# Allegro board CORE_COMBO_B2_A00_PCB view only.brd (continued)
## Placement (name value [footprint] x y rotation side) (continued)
PC5842  -  [NB_C0402_SMALL]  72.96 108.83 90 top
PC5843  -  [NB_C0402_SMALL]  68.72 123.05 90 top
PC5901  -  [NB_C0402_SMALL]  106.01 125.08 90 top
PC5902  -  [NB_C0402_SMALL]  115.13 128.13 270 top
PC5903  -  [NB_C0805_H55_SMALL]  120.2 131.05 270 top
PC5904  -  [NB_C0805_H55_SMALL]  116.14 127.75 270 bottom
PC5905  -  [NB_C0805_H55_SMALL]  112.08 127.88 270 bottom
PC5906  -  [NB_C0805_H55_SMALL]  121.98 131.05 270 top
PC5908  -  [C3528_H79]  117.39 129.66 90 top
PC5909  -  [NB_C0603_H35_SMALL]  108.93 130.09 180 top
PC5910  -  [NB_C0402_SMALL]  126.25 128.03 180 top
PC5911  -  [NB_C0603_H39_SMALL]  126.22 130.39 180 top
PC5912  -  [NB_C7343D_H79]  118.68 119.92 270 top
PC5913  -  [NB_C0603_H39_SMALL]  126.22 129.12 180 top
PC5914  -  [NB_C0603_H35_SMALL]  119.14 125.67 0 top
PC5915  -  [NB_C0402_SMALL]  123 128.39 90 top
PC5916  -  [NB_C0402_SMALL]  60.03 96.73 0 top
PC5917  -  [NB_C0805_H55_SMALL]  69.45 89.47 0 bottom
PC5918  -  [NB_C0805_H55_SMALL]  57.34 95.95 180 top
PC5919  -  [NB_C0805_H55_SMALL]  60.01 98.16 0 top
PC5920  -  [NB_C0805_H55_SMALL]  59.5 101.97 0 top
PC5921  -  [C3528_H79]  69.2 94.64 270 bottom
PC5922  -  [C3528_H79]  60.54 97.32 180 bottom
PC5923  -  [NB_C0603_H35_SMALL]  121.22 125.85 90 top
PC5924  -  [NB_C0603_H35_SMALL]  124.52 126.23 90 bottom
PC5925  -  [NB_C0402_SMALL]  64.96 90.67 0 top
PC5926  -  [NB_C0603_H35_SMALL]  56.96 92.19 180 top
PC5927  -  [NB_C7343D_H79]  68.51 101.21 0 top
PC5928  -  [NB_C0603_H35_SMALL]  62.28 99.83 180 top
PC5929  -  [NB_C7343D_H79]  114.87 120.26 270 bottom
PC5930  -  [NB_C7343D_H79]  68.29 100.29 0 bottom
PC5931  -  [C3528_H79]  65.52 94.64 270 bottom
PC5932  -  [C3528_H79]  119.42 131.2 180 bottom
PC6001  -  [NB_C0603_H39_SMALL]  114.49 110.86 0 top
PC6003  -  [NB_C0603_H39_SMALL]  114.49 112.13 0 top
PC6004  -  [NB_C0603_H39_SMALL]  114.49 109.59 0 top
PC6005  -  [NB_C0603_H39_SMALL]  107.63 113.66 180 top
PC6006  -  [NB_C0603_H39_SMALL]  107.63 114.93 180 top
PC6007  -  [NB_C0603_H39_SMALL]  107.63 116.2 180 top
PC6008  -  [NB_C0603_H39_SMALL]  114.49 113.37 0 top
PC6009  -  [NB_C0603_H39_SMALL]  107.63 109.88 180 top
PC6010  -  [NB_C0603_H39_SMALL]  114.49 114.62 0 top
PC6011  -  [NB_C0603_H39_SMALL]  107.63 112.42 180 top
PC6012  -  [NB_C0603_H39_SMALL]  107.63 111.15 180 top
PC6013  -  [NB_C0603_H39_SMALL]  118.04 91.3 180 top
PC6014  -  [NB_C0603_H39_SMALL]  108.34 92.88 0 top
PC6015  -  [NB_C0603_H39_SMALL]  106.17 98.16 0 top
PC6016  -  [NB_C0603_H39_SMALL]  103.96 98.16 0 top
PC6017  -  [NB_C0603_H39_SMALL]  95.06 97.65 90 top
PC6018  -  [NB_C0603_H39_SMALL]  93.66 97.65 90 top
PC6019  -  [NB_C0603_H39_SMALL]  108.34 91.61 0 top
PC6020  -  [NB_C0603_H39_SMALL]  103.54 89.05 180 top
PC6021  -  [NB_C0603_H39_SMALL]  106.11 89.02 0 top
PC6022  -  [NB_C0603_H39_SMALL]  108.34 95.42 0 top
PC6023  -  [NB_C0603_H39_SMALL]  108.34 94.15 0 top
PC6024  -  [NB_C0603_H39_SMALL]  122.36 98.24 180 top
PC6025  -  [NB_C0603_H39_SMALL]  123.02 111.11 180 top
PC6026  -  [NB_C0603_H39_SMALL]  98.23 90.08 270 top
PC6027  -  [NB_C0603_H39_SMALL]  96.99 90.08 270 top
PC6029  -  [NB_C0603_H39_SMALL]  108.34 90.34 0 top
PC6035  -  [NB_C0603_H39_SMALL]  114.49 113.4 0 bottom
PC6038  -  [NB_C0603_H39_SMALL]  114.49 112.13 0 bottom
PC6040  -  [NB_C0603_H39_SMALL]  114.49 109.64 0 bottom
PC6041  -  [NB_C0603_H39_SMALL]  114.49 110.88 0 bottom
PC6042  -  [NB_C0603_H39_SMALL]  120.97 90.79 0 top
PC6043  -  [NB_C0603_H39_SMALL]  120.97 92.01 0 top
PC6044  -  [NB_C0603_H39_SMALL]  92.34 89.24 270 top
PC6045  -  [NB_C0603_H39_SMALL]  91.12 89.24 270 top
PC6046  -  [NB_C0603_H39_SMALL]  81.85 96.38 90 bottom
PC6047  -  [NB_C0603_H39_SMALL]  80.58 96.38 90 bottom
PC6048  -  [NB_C0603_H39_SMALL]  83.12 96.38 90 bottom
PC6049  -  [NB_C0603_H39_SMALL]  84.39 96.38 90 bottom
PC6050  -  [NB_C0603_H39_SMALL]  89.54 96.37 90 bottom
PC6051  -  [NB_C0603_H39_SMALL]  88.27 96.37 90 bottom
PC6052  -  [NB_C0603_H39_SMALL]  86.94 96.37 90 bottom
PC6053  -  [NB_C0603_H39_SMALL]  85.67 96.37 90 bottom
PC6056  -  [NB_C0603_H39_SMALL]  109.36 118.61 90 bottom
PC6057  -  [NB_C0603_H39_SMALL]  111.8 118.61 90 bottom
PC6058  -  [NB_C0603_H39_SMALL]  112.84 95.37 180 top
PC6059  -  [NB_C0603_H39_SMALL]  112.84 94.12 180 top
PC6060  -  [NB_C0603_H39_SMALL]  112.84 92.88 180 top
PC6061  -  [NB_C0603_H39_SMALL]  112.84 91.63 180 top
PC6062  -  [NB_C0603_H39_SMALL]  120.97 94.45 0 top
PC6063  -  [NB_C0603_H39_SMALL]  115.81 93.82 0 top
PC6064  -  [NB_C0603_H39_SMALL]  115.81 92.57 0 top
PC6065  -  [NB_C0603_H39_SMALL]  115.81 91.3 0 top
PC6066  -  [NB_C0603_H39_SMALL]  85.91 89.65 270 bottom
PC6067  -  [NB_C0603_H39_SMALL]  87.16 89.65 270 bottom
PC6068  -  [NB_C0603_H39_SMALL]  90.87 89.65 270 bottom
PC6069  -  [NB_C0603_H39_SMALL]  89.63 89.65 270 bottom
PC6070  -  [NB_C0603_H39_SMALL]  88.4 89.65 270 bottom
PC6071  -  [NB_C0603_H39_SMALL]  92.1 89.65 270 bottom
PC6072  -  [NB_C0603_H39_SMALL]  120.97 93.23 0 top
PC6073  -  [NB_C0603_H39_SMALL]  82.1 89.65 270 bottom
PC6074  -  [NB_C0603_H39_SMALL]  83.37 89.65 270 bottom
PC6075  -  [NB_C0603_H39_SMALL]  84.64 89.65 270 bottom
PC6076  -  [C0201]  123.02 110.12 180 top
PC6077  -  [C0201]  123.02 109.39 180 top
PC6078  -  [C0201]  124.12 97.12 270 top
PC6079  -  [C0201]  124.45 89.12 0 top
PC6080  -  [C0201]  124.45 90.64 0 top
PC6081  -  [C0201]  124.45 89.85 0 top
PC6082  -  [C0201]  124.12 98.49 0 top
PC6083  -  [C0201]  114.87 97.04 0 top
PC6084  -  [C0201]  118.04 97.68 180 top
PC6085  -  [C0201]  114.62 89.52 180 top
PC6086  -  [C0201]  116.14 95.16 180 top
PC6087  -  [C0201]  117.54 88.79 180 top
PC6088  -  [C0201]  114.87 97.8 0 top
PC6089  -  [C0201]  118.68 95.9 180 top
PC6090  -  [C0201]  112.58 96.36 180 top
PC6091  -  [C0201]  114.87 95.57 0 top
PC6092  -  [C0201]  117.41 95.9 180 top
PC6093  -  [C0201]  94.22 89.47 270 top
PC6094  -  [C0201]  108.52 98.16 90 top
PC6095  -  [C0201]  109.28 98.16 90 top
PC6096  -  [C0201]  94.96 89.47 270 top
PC6097  -  [C0201]  107.76 98.16 90 top
PC6098  -  [C0201]  110.04 98.16 90 top
PC6099  -  [C0201]  98.87 93.46 270 top
PC6100  -  [C0201]  99.21 96.84 90 top
PC6101  -  [C0201]  98.46 96.84 90 top
PC6102  -  [C0201]  97.6 93.46 270 top
PC6103  -  [C0201]  117.41 95.16 180 top
PC6104  -  [C0201]  114.87 94.81 0 top
PC6105  -  [C0201]  114.62 90.29 180 top
PC6106  -  [C0201]  116.14 95.9 180 top
PC6107  -  [C0201]  113.63 97.75 180 top
PC6108  -  [C0201]  118.68 95.16 180 top
PC6109  -  [C0201]  119.06 89.54 0 top
PC6110  -  [C0201]  119.06 90.29 0 top
PC6111  -  [C0201]  117.54 89.52 180 top
PC6112  -  [C0201]  116.27 88.79 0 top
PC6113  -  [C0201]  93.48 89.47 270 top
PC6114  -  [C0201]  99.25 90.11 270 top
PC6115  -  [C0201]  93.61 92.01 270 bottom
PC6116  -  [C0201]  91.76 96.51 90 bottom
PC6117  -  [C0201]  116.14 97.8 180 top
PC6118  -  [C0201]  116.27 89.52 0 top
PC6119  -  [C0201]  113.63 98.47 180 top
PC6120  -  [C0201]  117.54 90.29 180 top
PC6121  -  [C0201]  116.27 90.29 0 top
PC6122  -  [C0201]  114.62 88.79 180 top
PC6123  -  [NB_C0603_H39_SMALL]  118.04 92.57 180 top
PC6125  -  [NB_C0603_H39_SMALL]  124.24 95.87 0 top
PC6126  -  [NB_C0603_H39_SMALL]  114.49 114.67 0 bottom
PC6127  -  [C0201]  119.06 88.79 0 top
PC6128  -  [C0201]  120.64 98.59 0 top
PC6129  -  [C0201]  120.64 97.85 0 top
PC6130  -  [NB_C0603_H39_SMALL]  118.04 93.82 180 top
PC6131  -  [C0201]  120.64 97.12 0 top
PC6132  -  [NB_C0603_H39_SMALL]  110.58 118.61 90 bottom
PC6133  -  [NB_C0603_H39_SMALL]  122.03 96 180 top
PC6134  -  [C0201]  120.2 96.15 0 top
PC6135  -  [C0201]  120.2 95.42 0 top
PC6136  -  [NB_C0603_H39_SMALL]  123.02 112.33 180 top
PC6137  -  [NB_C0603_H39_SMALL]  123.02 114.77 180 top
PC6138  -  [C0201]  116.14 98.54 180 top
PC6139  -  [NB_C0603_H39_SMALL]  90.78 96.37 90 bottom
PC6140  -  [NB_C0603_H39_SMALL]  129.1 114.75 0 top
PC6141  -  [C0201]  114.87 98.54 0 top
PC6142  -  [C0201]  114.87 96.3 0 top
PC6143  -  [NB_C0603_H39_SMALL]  123.02 113.55 180 top
PC6144  -  [NB_C0603_H39_SMALL]  129.1 113.53 0 top
PC6145  -  [NB_C0603_H39_SMALL]  129.1 112.26 0 top
PC6146  -  [NB_C0603_H39_SMALL]  129.1 110.99 0 top
PC6147  -  [NB_C0603_H39_SMALL]  129.09 109.74 0 top
PC7401  -  [NB_C0603_H39_SMALL]  188.58 24.91 180 top
PC7403  -  [NB_C0603_H39_SMALL]  183.6 22.42 180 bottom
PC7404  -  [NB_C0603_H34_SMALL]  190.03 22.87 270 top
PC7405  -  [NB_C0402_SMALL]  191.2 23.48 180 bottom
PC7406  -  [NB_C0402_SMALL]  195.77 24.93 90 top
PC7407  -  [R0603_H24]  187.31 26.94 270 top
PC7409  -  [NB_C0603_H39_SMALL]  186.04 24.91 0 top
PD5101  -  [ESD_2P_33_39X24_H17]  163.51 32.12 180 bottom
PD5102  -  [ESD_2P_33_39X24_H17]  163.51 33.52 180 bottom
PD5103  -  [ESD_2P_33_39X24_H17]  163.51 34.79 180 bottom
PD5201  -  [POWERDI5_3P_157X256]  221.85 24.25 90 top
PD5202  -  [POWERDI5_3P_157X256]  203.01 26.49 0 top
PD5205  -  [POWERDI5_3P_157X256]  165.9 26.41 180 top
PD5206  -  [SOT323]  228.77 31.88 90 top
PH5801  -  [NB_R0402_H24_SMALL]  60.01 90.67 0 top
PH5802  -  [R0402]  122.74 116.83 270 top
PH5803  -  [R0402]  108.01 118.22 90 top
PH5804  -  [NB_R0402_H24_SMALL]  108.52 125.08 90 top
PH5805  -  [R0402]  71.94 90.67 180 top
PJP6  -  [1MM_OPEN_5MIL_M1M2]  269.81 49.14 90 top
PJP7  -  [1MM_OPEN_5MIL_M1M2]  242.07 65.32 180 top
PJP10  -  [1MM_OPEN_5MIL_M1M2]  40.7 104.38 0 top
PJP802  -  [1MM_OPEN_5MIL_M1M2]  196.58 39.82 270 bottom
PJP803  -  [1MM_OPEN_5MIL_M1M2]  35.37 104.38 0 top
PJP805  -  [1MM_OPEN_5MIL_M1M2]  210.63 147.56 180 top
PJP3301  -  [1MM_OPEN_5MIL_M1M2]  183.07 123.81 0 top
PJP5201  -  [NB_PWR_FB_SHORT_PT]  212.91 23.74 0 top
PJP5202  -  [NB_PWR_FB_SHORT_PT]  214.69 23.74 180 top
PJP5203  -  [NB_PWR_FB_SHORT_PT]  177.35 31.1 180 top
PJP5204  -  [NB_PWR_FB_SHORT_PT]  175.58 31.1 0 top
PJP5301  -  [3MM_OPEN_5MIL_M1M2]  187.58 76.8 90 top
PJP5302  -  [3MM_OPEN_5MIL_M1M2]  205.48 49.39 90 top
PJP5303  -  [NB_PWR_FB_SHORT_PT]  179 72.89 180 bottom
PJP5304  -  [NB_PWR_FB_SHORT_PT]  179 74.28 180 bottom
PJP5305  -  [NB_PWR_FB_SHORT_PT]  200.47 48.38 0 top
PJP5306  -  [1MM_OPEN_5MIL_M1M2]  198.56 62.6 0 bottom
PJP5307  -  [1MM_OPEN_5MIL_M1M2]  191.32 67.17 90 top
PJP5308  -  [3MM_OPEN_5MIL_M1M2]  205.48 55.23 90 top
PJP5401  -  [3MM_OPEN_5MIL_M1M2]  93.34 72.38 90 top
PJP5402  -  [1MM_OPEN_5MIL_M1M2]  88.2 48.63 90 top
PJP5403  -  [1MM_OPEN_5MIL_M1M2]  92.01 52.95 90 top
PJP5404  -  [3MM_OPEN_5MIL_M1M2]  94.87 66.79 90 top
PJP5501  -  [3MM_OPEN_5MIL_M1M2]  144.71 118.48 0 top
PJP5502  -  [3MM_OPEN_5MIL_M1M2]  136.33 119.56 0 bottom
PJP5601  -  [1MM_OPEN_5MIL_M1M2]  170.29 71.87 0 bottom
PJP5602  -  [2MM_OPEN_5MIL_M1M2]  171.54 87.58 270 bottom
PJP5603  -  [1MM_OPEN_5MIL_M1M2]  173.98 107.68 90 bottom
PJP5604  -  [2MM_OPEN_5MIL_M1M2]  173.67 92.93 0 bottom
PJP5701  -  [1MM_OPEN_5MIL_M1M2]  211.9 62.6 0 top
PJP5702  -  [1MM_OPEN_5MIL_M1M2]  217.03 56.45 270 top
PJP5703  -  [1MM_OPEN_5MIL_M1M2]  190.05 103.87 180 top
PJP5704  -  [1MM_OPEN_5MIL_M1M2]  185.48 114.03 270 top
PJP5705  -  [1MM_OPEN_5MIL_M1M2]  211.01 48.63 90 top
PJP5706  -  [1MM_OPEN_5MIL_M1M2]  216.72 48.58 270 top
PJP5707  -  [1MM_OPEN_5MIL_M1M2]  65.85 127.12 90 top
PJP5708  -  [1MM_OPEN_5MIL_M1M2]  69.96 130.93 0 top
PJP5806  -  [1MM_OPEN_5MIL_M1M2]  160.06 125.57 180 bottom
PJP5809  -  [1MM_OPEN_5MIL_M1M2]  153.48 65.27 90 bottom
PJP5810  -  [3MM_OPEN_5MIL_M1M2]  158.56 36.95 270 top
PJP5811  -  [1MM_OPEN_5MIL_M1M2]  200.21 144.77 270 bottom
PJP5812  -  [1MM_OPEN_5MIL_M1M2]  196.91 50.71 270 bottom
PJP5813  -  [1MM_OPEN_5MIL_M1M2]  84.59 111.32 270 bottom
PJP5815  -  [1MM_OPEN_5MIL_M1M2]  90.49 117.59 0 top
PJP5901  -  [NB_PWR_FB_SHORT_PT]  112.46 121.53 90 top
PJP5902  -  [NB_PWR_FB_SHORT_PT]  112.46 117.97 270 top
PJP5903  -  [NB_PWR_FB_SHORT_PT]  126.17 120.64 90 top
PJP5904  -  [NB_PWR_FB_SHORT_PT]  126.17 117.84 270 top
PJP5905  -  [NB_PWR_FB_SHORT_PT]  66.99 94.99 180 top
PJP5906  -  [NB_PWR_FB_SHORT_PT]  70.55 94.99 0 top
PJP5908  -  [2MM_OPEN_5MIL_M1M2]  150.43 114.25 270 top
PJP5909  -  [1MM_OPEN_5MIL_M1M2]  38.93 116.13 180 top
PJP5911  -  [3MM_OPEN_5MIL_M1M2]  186.12 81.31 180 top
PJP5912  -  [1MM_OPEN_5MIL_M1M2]  93.15 115.69 270 top
PJP5913  -  [1MM_OPEN_5MIL_M1M2]  69.96 130.93 180 bottom
PL5101  -  [L0805_H41]  155.51 29.71 0 top
PL5102  -  [L0805_H41]  155.51 27.55 0 top
PL5103  -  [NB_L0603_H37_SMALL]  241.74 41.9 270 top
PL5104  -  [L0805_H41]  29.91 91.18 0 top
PL5201  -  [L0805_H41]  224.47 32.75 90 top
PL5202  -  [NB_INDUCTOR_2P_427X394]  198.18 38.34 180 top
PL5301  -  [NB_INDUCTOR_2P_287X260_H94]  186.62 73.14 0 bottom
PL5302  -  [L0805_H41]  182.18 61.71 180 top
PL5303  -  [L0805_H41]  182.18 59.55 180 top
PL5304  -  [INDUCTOR_2P_287X260]  198.44 54.34 0 top
PL5401  -  [L0805_H41]  78.93 60.44 270 top
PL5402  -  [INDUCTOR_2P_287X260]  83.88 70.6 270 top
PL5501  -  [L0805_H41]  133.52 127.04 270 bottom
PL5502  -  [INDUCTOR_2P_213X205]  133.92 118.48 270 top
PL5601  -  [INDUCTOR_2P_150X150_CYN]  172.27 82.67 90 bottom
PL5602  -  [INDUCTOR_2P_150X150_CYN]  172.13 97.8 270 bottom
PL5701  -  [INDUCTOR_2P_79X63_CY]  218.12 60.64 0 top
PL5702  -  [INDUCTOR_2P_79X63_CY]  188.91 112.13 90 top
PL5703  -  [INDUCTOR_2P_79X63_CY]  217.96 52.95 0 top
PL5704  -  [INDUCTO_2P_98X79_CYNTEC_H47]  71.29 138.18 0 top
PL5901  -  [INDUCTOR_2P_278X260_H118]  112.46 119.75 270 top
PL5902  -  [L0805_H41]  125.06 132.07 0 top
PL5903  -  [L0805_H41]  128.38 131.05 90 top
PL5904  -  [L0805_H41]  67.88 83.3 270 bottom
PL5905  -  [INDUCTOR_2P_197X185]  126.18 119.23 270 top
PL5906  -  [INDUCTOR_2P_278X260_H118]  68.77 94.99 0 top
PL7401  -  [L1008_TAIYO_H47]  187.16 22.95 180 top
PQ5101  -  [SOT23_H43]  244.66 41.39 0 top
PQ5102  -  [SOT23_FAIR]  248.8 39.87 90 top
PQ5103  -  [SOIC_8P_50_196X236]  70.62 81.27 180 top
PQ5104  -  [SOT666_H20]  75.37 68.92 0 top
PQ5105  -  [SOT23]  71.82 87.36 270 top
PQ5106  -  [SOT363_PHILIPS]  72.83 71.24 0 top
PQ5201  -  [POWER33_5P]  224.34 28.56 90 top
PQ5202  -  [SOT363_PHILIPS]  251.01 26.79 180 top
PQ5203  -  [SOT23]  247.84 24.12 90 top
PQ5204  -  [SOT23]  236.79 24.12 90 top
PQ5205  -  [SOT23]  240.09 24.12 90 top
PQ5206  -  [SOT23]  233.49 24.12 90 top
PQ5207  -  [SOT23]  230.06 24.12 90 top
PQ5208  -  [POWER33_5P]  208.21 25.77 0 top
PQ5209  -  [SOT23_2D4_H43]  198.82 24.12 0 top
PQ5210  -  [SOT363_PHILIPS]  257.36 26.79 180 top
PQ5211  -  [SOT23_2D4_H43]  243.52 24.12 0 top
PQ5212  -  [SOT23_2D4_H43]  248.35 30.6 90 top
PQ5213  -  [SOT23]  254.32 24.12 90 top
PQ5214  -  [SOT363_PHILIPS]  250.25 33.77 270 top
PQ5215  -  [SOT23_2D4_H43]  254.44 30.6 90 top
PQ5216  -  [SOT23_2D4_H43]  254.44 34.28 270 top
PQ5217  -  [SOT23_2D4_H43]  244.03 28.06 90 top
PQ5218  -  [DFN_7P_50_197X236]  208.6 33.77 0 top
PQ5219  -  [SOIC_8P_50_197X236]  160.72 27.42 0 top
PQ5220  -  [SOT363_PHILIPS]  230.19 38.72 180 top
PQ5301  -  [POWERPAIR_8P_2PAD_VISHAY]  185.86 69.08 270 top
PQ5302  -  [SOP_8P_SPE_FAIRCHILD]  190.56 54.6 180 top
PQ5401  -  [SOP_8P_SPE_FAIRCHILD]  83.88 62.86 270 top
PQ5902  -  [POWERPAIR_8P_2PAD_VISHAY]  127.17 125.75 90 top
PR5101  -  [NB_R0402_SMALL]  165.37 32.12 180 bottom
PR5102  -  [NB_R0402_SMALL]  167.19 34.79 0 bottom
PR5103  -  [NB_R0402_SMALL]  165.49 33.52 180 bottom
PR5104  -  [NB_R0402_SMALL]  165.54 34.79 180 bottom
PR5105  -  [NB_R0402_SMALL]  250 42.53 0 top
PR5106  -  [NB_R0402_SMALL]  247.71 42.53 0 top
PR5107  -  [NB_R0402_SMALL]  241.74 39.23 270 top
PR5108  -  [NB_R0402_SMALL]  249.87 36.31 270 top
PR5109  -  [NB_R0402_SMALL]  248.98 36.31 270 top
PR5110  -  [NB_R0402_SMALL]  241.74 37.33 90 top
PR5112  -  [NB_R0402_SMALL]  69.78 86.22 90 top
PR5113  -  [NB_R0402_SMALL]  69.15 73.78 0 top
PR5114  -  [NB_R0402_SMALL]  69.78 87.82 90 top
PR5115  -  [NB_R0402_SMALL]  68.9 86.22 90 top
PR5116  -  [NB_R0402_SMALL]  67.75 86.22 270 top
PR5117  -  [NB_R0402_SMALL]  74.89 66.28 180 top
PR5118  -  [NB_R0402_SMALL]  168.08 31.61 0 bottom
PR5201  -  [R0603_H24]  251.65 23.36 270 top
PR5202  -  [R1206_H33]  213.8 23.74 0 top
PR5203  -  [R0603_H24]  250.25 23.36 270 top
PR5204  -  [NB_R0402_SMALL]  251.39 29.33 0 top
PR5205  -  [NB_R0402_SMALL]  247.2 27.17 180 top
PR5206  -  [NB_R0402_SMALL]  199.45 26.79 0 top
PR5207  -  [NB_R0402_SMALL]  236.43 26.81 180 top
PR5208  -  [NB_R0402_SMALL]  248.85 27.17 180 top
PR5209  -  [NB_R0402_SMALL]  238.09 26.81 0 top
PR5210  -  [R0603_H24]  258 23.36 270 top
PR5211  -  [NB_R0402_SMALL]  251.39 30.21 0 top
PR5212  -  [NB_R0402_SMALL]  251.39 31.1 180 top
PR5213  -  [R0603_H24]  256.6 23.36 270 top
PR5214  -  [NB_R0402_SMALL]  255.2 28.31 180 top
PR5215  -  [NB_R0402_SMALL]  253.43 27.17 180 top
PR5216  -  [NB_R0402_SMALL]  247.61 33.26 270 top
PR5217  -  [NB_R0603_H22_SMALL]  236.28 28.82 270 top
PR5218  -  [NB_R0402_SMALL]  255.46 36.56 0 top
PR5219  -  [NB_R0402_SMALL]  255.08 27.17 180 top
PR5220  -  [NB_R0402_SMALL]  253.81 36.56 0 top
PR5221  -  [NB_R0402_SMALL]  241.44 27.14 90 top
PR5222  -  [NB_R0603_H22_SMALL]  237.55 28.82 270 top
PR5223  -  [NB_R0402_SMALL]  171.33 32.6 0 bottom
PR5224  -  [NB_R0402_SMALL]  239.74 26.81 0 top
PR5225  -  [NB_R0402_SMALL]  245.3 30.6 180 top
PR5226  -  [NB_R0402_SMALL]  240.85 29.1 270 top
PR5227  -  [R0402]  239.81 29.1 90 top
PR5228  -  [NB_R0402_SMALL]  243.14 30.6 0 top
PR5229  -  [NB_R0402_SMALL]  243.14 31.48 0 top
PR5230  -  [NB_R0805_H24_SMALL]  230.69 28.56 180 top
PR5231  -  [NB_R0402_SMALL]  243.14 32.37 0 top
PR5232  -  [NB_R0402_SMALL]  240.85 32.37 0 top
PR5233  -  [R1206_H33]  176.47 31.11 180 top
PR5234  -  [NB_R0603_H24_SMALL]  231.96 33.29 0 top
PR5235  -  [NB_R0805_H24_SMALL]  206.82 39.23 0 top
PR5236  -  [NB_R0402_SMALL]  245.3 32.25 0 top
PR5237  -  [NB_R0402_SMALL]  244.91 34.77 270 top
PR5238  -  [NB_R0402_SMALL]  243.06 33.32 0 top
PR5239  -  [NB_R0402_SMALL]  243.06 34.17 0 top
PR5240  -  [NB_R0402_SMALL]  243.14 35.04 0 top
PR5241  -  [NB_R0402_SMALL]  243.14 35.93 0 top
PR5242  -  [NB_R0402_SMALL]  234.63 36.44 0 top
PR5243  -  [NB_R0402_SMALL]  242.76 37.45 90 top
PR5244  -  [NB_R0402_SMALL]  243.65 37.45 270 top
PR5245  -  [NB_R0402_SMALL]  239.71 39.13 90 top
PR5246  -  [NB_R0402_SMALL]  240.73 37.45 90 top
PR5247  -  [NB_R0603_H22_SMALL]  166.05 24.63 180 bottom
PR5248  -  [NB_R0402_SMALL]  239.84 37.45 270 top
PR5249  -  [R0603_H24]  237.78 39.56 180 top
PR5250  -  [NB_R0402_SMALL]  232.34 40.81 270 top
PR5251  -  [NB_R0402_SMALL]  233.23 40.81 270 top
PR5252  -  [NB_R0402_H15_SMALL]  227.75 43.02 270 top
PR5253  -  [NB_R0402_SMALL]  225.79 43.12 90 top
PR5254  -  [NB_R0402_SMALL]  224.9 41.47 270 top
PR5255  -  [NB_R0402_SMALL]  231.07 36.13 0 top
PR5256  -  [NB_R0402_SMALL]  225.79 41.47 90 top
PR5257  -  [NB_R0402_SMALL]  230.08 35.24 0 top
PR5258  -  [NB_R0402_SMALL]  224.9 43.12 90 top
PR5259  -  [NB_R0402_SMALL]  224.01 41.47 90 top
PR5260  -  [NB_R0402_SMALL]  215.07 43.96 90 top
PR5261  -  [NB_R0402_SMALL]  224.9 45.28 270 top
PR5262  -  [NB_R0402_SMALL]  230.31 41.14 0 top
PR5263  -  [NB_R0402_SMALL]  226.86 44.08 270 top
PR5264  -  [NB_R0402_SMALL]  171.33 33.44 0 bottom
PR5301  -  [VX_R0805_H24_SMALL]  190.18 72.63 270 top
PR5302  -  [NB_R0603_H24_SMALL]  196.28 66.92 270 top
PR5303  -  [NB_R0603_H24_SMALL]  196.78 59.17 270 top
PR5304  -  [NB_R0402_SMALL]  191.83 59.88 180 top
PR5305  -  [VX_R0805_H24_SMALL]  191.7 48.76 180 top
PR5306  -  [NB_R0402_SMALL]  193.61 59.88 180 top
PR5307  -  [NB_R0402_SMALL]  194.96 68.92 270 top
PR5308  -  [NB_R0402_SMALL]  191.37 61.89 0 top
PR5309  -  [NB_R0402_SMALL]  193.48 68.19 180 top
PR5310  -  [NB_R0402_SMALL]  190.82 63.11 270 top
PR5311  -  [NB_R0402_SMALL]  193.48 67.3 180 top
PR5312  -  [NB_R0402_SMALL]  191.7 63.11 90 top
PR5313  -  [NB_R0402_H16_SMALL]  191.83 60.85 0 top
PR5401  -  [NB_R0603_H24_SMALL]  84.31 49.42 0 top
PR5402  -  [NB_R0402_SMALL]  79.56 54.34 270 top
PR5403  -  [NB_R0805_H24_SMALL]  79.31 70.47 90 top
PR5404  -  [NB_R0603_H22_SMALL]  80.63 54.12 90 top
PR5405  -  [R0402]  87.76 55.54 270 top
PR5406  -  [NB_R0402_SMALL]  83.04 56.27 270 top
PR5407  -  [NB_R0402_SMALL]  84.82 56.66 180 top
PR5408  -  [NB_R0402_SMALL]  89.93 55.84 0 top
PR5409  -  [NB_R0402_SMALL]  86.47 56.15 270 top
PR5501  -  [NB_R0402_SMALL]  130.85 124.14 270 top
PR5502  -  [NB_R0603_H22_SMALL]  133.54 128.72 90 top
PR5503  -  [NB_R0603_H22_SMALL]  137.86 121.15 270 top
PR5504  -  [NB_R0402_SMALL]  130.87 126.48 180 top
PR5505  -  [NB_R0402_SMALL]  131.25 127.75 90 top
PR5506  -  [NB_R0402_SMALL]  131.68 124.38 90 top
PR5507  -  [NB_R0402_SMALL]  130.11 120.87 0 top
PR5508  -  [NB_R0402_SMALL]  131.94 125.59 180 top
PR5509  -  [NB_R0402_SMALL]  130.11 121.7 180 top
PR5601  -  [NB_R0402_SMALL]  176.82 77.48 180 bottom
PR5602  -  [NB_R0402_SMALL]  175.7 79.26 0 bottom
PR5603  -  [NB_R0402_SMALL]  176.22 80.63 90 bottom
PR5604  -  [NB_R0402_SMALL]  175.37 80.63 90 bottom
PR5605  -  [NB_R0603_H22_SMALL]  168.84 80.89 0 bottom
PR5606  -  [NB_R0402_SMALL]  176.82 76.62 180 bottom
PR5607  -  [NB_R0402_SMALL]  167.83 78.22 180 bottom
PR5608  -  [NB_R0402_SMALL]  175.17 77.48 180 bottom
PR5609  -  [NB_R0402_SMALL]  175.17 76.62 180 bottom
PR5610  -  [NB_R0402_SMALL]  167.83 74.66 0 bottom
PR5611  -  [NB_R0402_SMALL]  167.83 77.33 180 bottom
PR5612  -  [NB_R0402_SMALL]  167.83 75.55 180 bottom
PR5613  -  [NB_R0402_SMALL]  167.57 103.32 270 bottom
PR5614  -  [NB_R0402_SMALL]  168.84 103.32 90 bottom
PR5615  -  [NB_R0603_H22_SMALL]  175.51 98.69 180 bottom
PR5616  -  [NB_R0402_SMALL]  167.57 106.87 270 bottom
PR5617  -  [NB_R0402_SMALL]  168.84 106.87 270 bottom
PR5618  -  [NB_R0402_SMALL]  175.45 101.69 0 bottom
PR5619  -  [NB_R0402_SMALL]  167.57 105.22 270 bottom
PR5620  -  [NB_R0402_SMALL]  168.84 105.22 270 bottom
PR5621  -  [NB_R0402_SMALL]  175.45 105.14 180 bottom
PR5622  -  [NB_R0402_SMALL]  175.45 102.55 0 bottom
PR5623  -  [NB_R0402_SMALL]  175.45 104.28 0 bottom
PR5701  -  [NB_R0402_SMALL]  218.02 63.72 270 top
PR5702  -  [NB_R0603_H22_SMALL]  216.85 58.66 0 top
PR5703  -  [NB_R0402_SMALL]  217.13 63.72 90 top
PR5704  -  [NB_R0402_SMALL]  214.23 63.59 90 top
PR5705  -  [NB_R0402_SMALL]  215.12 63.59 90 top
PR5706  -  [NB_R0402_SMALL]  184.95 110.25 270 top
PR5707  -  [NB_R0603_H22_SMALL]  190.82 111.62 90 top
PR5708  -  [NB_R0402_SMALL]  185.84 110.25 90 top
PR5709  -  [NB_R0402_SMALL]  186.73 108.22 90 top
PR5710  -  [NB_R0402_SMALL]  185.84 108.22 90 top
PR5711  -  [NB_R0402_SMALL]  214.44 56.76 0 top
PR5712  -  [NB_R0603_H22_SMALL]  216.8 50.79 0 top
PR5713  -  [NB_R0402_SMALL]  214.44 55.87 180 top
PR5714  -  [NB_R0402_SMALL]  212.28 54.73 180 top
PR5715  -  [NB_R0402_SMALL]  212.28 56.5 180 top
PR5716  -  [NB_R0402_SMALL]  66.23 136.39 90 top
PR5717  -  [NB_R0402_SMALL]  66.74 139.18 180 top
PR5718  -  [NB_R0603_H22_SMALL]  68.77 138.42 270 top
PR5719  -  [NB_R0402_SMALL]  66.74 140.32 0 top
PR5720  -  [NB_R0402_SMALL]  65.21 134.48 270 top
PR5801  -  [NB_R0402_SMALL]  64.45 120 270 top
PR5802  -  [NB_R0402_SMALL]  70.45 123.05 90 top
PR5803  -  [NB_R0402_SMALL]  67.83 123.05 90 top
PR5804  -  [NB_R0402_SMALL]  71.33 123.05 90 top
PR5805  -  [NB_R0402_SMALL]  72.22 123.05 270 top
PR5806  -  [NB_R0402_SMALL]  69.61 123.05 270 top
PR5807  -  [NB_R0402_SMALL]  69.86 120 270 top
PR5808  -  [NB_R0402_SMALL]  70.72 120 90 top
PR5809  -  [NB_R0402_SMALL]  71.59 120 90 top
PR5810  -  [NB_R0402_SMALL]  74.2 123.05 270 top
PR5811  -  [NB_R0402_SMALL]  68.82 120 90 top
PR5812  -  [NB_R0402_SMALL]  73.19 123.97 270 top
PR5813  -  [NB_R0402_SMALL]  67.75 116.45 0 top
PR5814  -  [NB_R0402_SMALL]  67.96 120 270 top
PR5815  -  [NB_R0402_SMALL]  77.89 116.47 180 top
PR5816  -  [NB_R0402_SMALL]  76.19 120.12 270 top
PR5817  -  [NB_R0402_SMALL]  67.07 120 270 top
PR5818  -  [NB_R0402_SMALL]  79.8 114.95 180 top
PR5819  -  [NB_R0402_SMALL]  77.07 120.12 270 top
PR5821  -  [NB_R0402_SMALL]  121.73 118.2 90 top
PR5822  -  [NB_R0402_SMALL]  65.46 115.78 0 top
PR5823  -  [NB_R0402_SMALL]  121.73 116.43 90 top
PR5824  -  [NB_R0402_SMALL]  66.23 120 270 top
PR5825  -  [NB_R0402_SMALL]  62.52 111.15 0 top
PR5826  -  [NB_R0402_SMALL]  62.52 113.73 0 top
PR5827  -  [NB_R0402_SMALL]  67.22 114.43 180 top
PR5828  -  [NB_R0402_SMALL]  79.49 111.72 0 top
PR5829  -  [NB_R0402_SMALL]  83.07 111.75 180 top
PR5830  -  [NB_R0402_SMALL]  85.41 111.49 270 top
PR5831  -  [NB_R0402_SMALL]  79.49 112.66 0 top
PR5832  -  [R0402]  84.44 111.49 270 top
PR5833  -  [NB_R0402_SMALL]  61.66 90.67 180 top
PR5834  -  [NB_R0402_SMALL]  69.28 105.02 90 top
PR5836  -  [NB_R0402_SMALL]  81.11 109.84 270 top
PR5838  -  [NB_R0402_SMALL]  79.18 109.82 90 top
PR5839  -  [NB_R0402_SMALL]  106.87 118.23 90 top
PR5840  -  [NB_R0402_SMALL]  69.28 106.67 90 top
PR5842  -  [NB_R0402_SMALL]  67.09 109.26 90 top
PR5843  -  [NB_R0402_SMALL]  108.01 120.26 90 top
PR5844  -  [NB_R0402_SMALL]  69.4 89.83 0 top
PR5845  -  [NB_R0402_SMALL]  69.4 90.67 0 top
PR5846  -  [NB_R0402_SMALL]  69.89 108.79 90 top
PR5847  -  [NB_R0402_SMALL]  64.86 110.25 180 top
PR5849  -  [NB_R0402_SMALL]  71.23 105.02 90 top
PR5850  -  [NB_R0402_SMALL]  71.23 106.92 270 top
PR5851  -  [NB_R0402_SMALL]  72.07 105.02 90 top
PR5853  -  [NB_R0402_SMALL]  64.78 109.39 180 top
PR5901  -  [NB_R0603_H24_SMALL]  108.93 131.33 0 top
PR5902  -  [VX_R0805_H24_SMALL]  116.09 125.41 180 top
PR5903  -  [NB_R0603_H24_SMALL]  106.87 120.26 90 top
PR5905  -  [NB_R0603_H24_SMALL]  122.36 122.42 180 top
PR5906  -  [VX_R0805_H24_SMALL]  124.37 123.31 270 bottom
PR5907  -  [NB_R0603_H24_SMALL]  122.87 119.57 90 top
PR5909  -  [NB_R0603_H24_SMALL]  56.96 93.41 0 top
PR5910  -  [VX_R0805_H24_SMALL]  63.04 97.75 270 top
PR5911  -  [NB_R0603_H24_SMALL]  67.12 90.54 180 top
PR5913  -  [NB_R0402_SMALL]  63.31 90.67 180 top
PR5914  -  [NB_R0402_SMALL]  57.82 91.17 0 top
PR5915  -  [NB_R0402_SMALL]  107.07 124.8 270 top
PR5916  -  [NB_R0402_SMALL]  108.67 129.02 0 top
PR6091  -  [NB_R0402_SMALL]  156.4 92.7 90 top
PR6092  -  [NB_R0402_SMALL]  67.63 142.99 180 top
PR7401  -  [NB_R0402_SMALL]  192.82 23.99 0 bottom
PR7402  -  [NB_R0402_SMALL]  191.2 24.35 180 bottom
PR7403  -  [NB_R0402_SMALL]  194.07 23.56 270 bottom
PR7404  -  [NB_R0603_H24_SMALL]  191.55 22.42 180 bottom
PR7405  -  [NB_R0402_SMALL]  196.12 23.61 0 top
PR7406  -  [NB_R0402_SMALL]  190.18 25.77 90 top
PR7408  -  [NB_R0402_SMALL]  182.46 25.69 180 top
PT5101  -  [NB_TPC28T_68]  255.33 42.28 0 top
PU1  -  [SC70_S6]  252.54 39.36 180 top
PU5201  -  [QFN_28P_16_157X157_PAD_4VIA]  236.66 33.01 0 top
PU5202  -  [SC70_S5]  233.19 38.47 180 top
PU5203  -  [SOIC_8P_50_196X236]  219.44 43.5 90 top
PU5301  -  [QFN_20P_16_S118_PAD_H31_2V]  195.9 63.11 270 top
PU5401  -  [QFN_20P_16_S118_PAD_H31_2V]  84.96 53.23 90 top
PU5501  -  [NB_QFN_10P_18_118X118_SILE]  135.36 125.42 90 top
PU5601  -  [QFN_16P_20_S118_PAD_MACO_4V]  171.77 78.09 0 bottom
PU5602  -  [QFN_16P_20_S118_PAD_MACO_4V]  171.51 102.48 180 bottom
PU5701  -  [DFN_8P_20_S79_P_SIL_H26_4V]  214.95 61.08 270 top
PU5702  -  [DFN_8P_20_S79_P_SIL_H26_4V]  188.91 108.95 0 top
PU5703  -  [DFN_8P_20_S79_P_SIL_H26_4V]  214.95 53.07 270 top
PU5801  -  [QFN_40P_16_197X197_PAD_8V]  71.56 113.65 270 top
PU5901  -  [SOP_9P_16_177X138_8V]  112.08 126.99 0 top
PU5902  -  [DFN_8P_20_S79_P_INT_H39_1V]  123.63 125.08 0 top
PU5903  -  [SOP_9P_16_177X138_8V]  61.4 93.71 90 top
PU5904  -  [DFN_8P_20_S79_P_SIL_H26_4V]  68.26 135.5 0 top
PU7401  -  [SOIC_8P_26_118X110_MAXI_H39]  193 23.71 270 top
PU7402  -  [DFN_6P_26_79X79_PAD_TI]  183.6 23.79 180 top
Q1  -  [SOT23_VISHAY]  40.7 107.56 0 top
Q2  -  [SOIC_8P_50_197X236]  48.45 109.84 270 top
Q4  -  [SOT23_2D4_H43]  45.91 103.62 0 top
Q5  -  [SOT363_PHILIPS]  246.06 45.58 270 top
Q11  -  [SOT23_FAIR]  153.73 106.67 0 bottom
Q12  -  [SOT23_FAIR]  246.29 62.57 0 top
Q14  -  [SOT23_FAIR]  196.63 22.82 180 bottom
Q16  -  [SOT323_INFINEON_H43]  268.41 11.67 90 top
Q17  -  [SOT363_PHILIPS]  46.42 98.29 0 top
Q19  -  [SOT363_PHILIPS]  190.18 43.19 180 bottom
Q22  -  [SOT363_PHILIPS]  29.1 131.18 180 top
Q23  -  [SOT363_PHILIPS]  260.79 11.67 180 top
Q25  -  [SOT363_PHILIPS]  271.84 11.67 0 top
Q28  -  [SOT363_PHILIPS]  265.24 11.67 0 top
Q30  -  [SOT363_PHILIPS]  26.18 131.18 180 top
Q32  -  [SOT363_PHILIPS]  160.34 134.23 270 top
Q33  -  [SOT363_PHILIPS]  158.94 131.31 90 top
Q122  -  [SOT363_PHILIPS]  19.37 123.43 90 top
Q144  -  [SOT323_INFINEON_H43]  261.68 7.61 0 top
Q216  -  [SOT23_VISHAY]  36.36 107.56 0 top
Q217  -  [SOT23_2D4_H43]  35.1 134.86 0 bottom
Q1701  -  [SOT23_2D4_H43]  89.7 117.29 90 bottom
Q3601  -  [SOT23_VISHAY]  210.5 144.08 270 top
Q3602  -  [SOT363_PHILIPS]  261.15 17.51 0 top
Q3603  -  [SOT23_FAIR]  155 68.64 0 bottom
Q3604  -  [SOT23_VISHAY]  156.65 126.35 90 bottom
Q3605  -  [SOT363_PHILIPS]  155.89 129.91 90 bottom
Q3606  -  [SOT23_2D4_H43]  39.69 130.83 90 bottom
Q3607  -  [SOT23_2D4_H43]  93.97 117.29 90 bottom
Q3609  -  [SOT23_VISHAY]  41.97 98.03 90 top
Q3610  -  [SOT23_VISHAY]  265.49 4.43 270 top
Q4199  -  [SOT23_VISHAY]  188.4 149.34 270 top
Q4200  -  [SOT23_2D4_H43]  192.09 149.34 0 top
Q4203  -  [SOT23_2D4_H43]  153.71 84.62 90 top
Q4209  -  [SOT363_PHILIPS]  34.94 136.49 0 top
Q4210  -  [SOT23_VISHAY]  58.23 117.48 180 top
Q4211  -  [SOT23_VISHAY]  58.23 121.02 180 top
Q4213  -  [SOT23_VISHAY]  43.27 112.69 180 bottom
Q4214  -  [SOT23_VISHAY]  51.24 112.71 0 bottom
Q4215  -  [SOT23_2D4_H43]  250.2 62.45 0 top
Q4216  -  [SOT23_VISHAY]  40.32 93.97 0 bottom
QC1  -  [SOT363_PHILIPS]  152.85 96.26 0 top
QC2807  -  [SOT363_PHILIPS]  188.78 134.35 90 top
QC2808  -  [SOT363_PHILIPS]  181.62 51.19 180 top
QZ22  -  [SOT363_PHILIPS]  19.37 120.51 90 top
R1  -  [NB_R0402_SMALL]  144.97 114.95 270 bottom
R2  -  [NB_R0402_SMALL]  151.9 120.38 180 bottom
R28  -  [NB_R0402_SMALL]  79.63 35.2 270 top
R32  -  [NB_R0402_SMALL]  79.63 32.9 270 top
R34  -  [NB_R0402_SMALL]  81.85 38.6 270 top
R35  -  [NB_R0402_SMALL]  243.27 44.82 0 top
R36  -  [NB_R0402_SMALL]  248.47 45.07 270 top
R44  -  [NB_R0402_SMALL]  94.88 124.88 0 top
R45  -  [VX_R0402_SMALL]  145.22 120 0 bottom
R47  -  [NB_R0402_SMALL]  94.88 124.04 0 top
R55  -  [NB_R0402_SMALL]  94.55 132.7 0 top
R57  -  [VX_R0402_SMALL]  155.89 121.78 270 bottom
R64  -  [NB_R0402_SMALL]  74.48 146.42 0 top
R65  -  [NB_R0402_SMALL]  80.71 143.37 90 top
R66  -  [NB_R0402_SMALL]  83.35 135.67 90 top
R74  -  [NB_R0402_SMALL]  81.91 133.38 180 top
R94  -  [NB_R0402_SMALL]  43.24 106.97 90 top
R95  -  [NB_R0402_SMALL]  51.7 97.15 90 bottom
R96  -  [NB_R0402_SMALL]  48.96 97.4 270 bottom
R97  -  [NB_R0402_SMALL]  43.24 108.71 90 top
R98  -  [NB_R0402_SMALL]  146.57 127.12 180 top
R99  -  [NB_R0402_SMALL]  44.08 106.97 270 top
R107  -  [NB_R0402_SHORT_25MIL]  81.77 135.88 0 top
R122  -  [NB_R0402_SMALL]  188.15 49.01 0 bottom
R123  -  [NB_R0402_SMALL]  188.15 47.74 0 bottom
R124  -  [NB_R0402_SMALL]  153.35 59.81 90 bottom
R125  -  [NB_R0402_SMALL]  188.33 43.12 270 bottom
R126  -  [NB_R0402_SMALL]  188.33 44.74 270 bottom
R130  -  [NB_R0805_H24_SMALL]  49.82 117.82 90 bottom
R136  -  [NB_R0402_SMALL]  49.34 123.89 180 top
R142  -  [VX_R0402_SMALL]  34.28 131.71 180 top
R148  -  [NB_R0402_SMALL]  49.34 121.53 180 top
R149  -  [NB_R0402_SMALL]  49.34 122.8 180 top
R152  -  [VX_R0402_SMALL]  45.53 128.61 180 top
R153  -  [VX_R0402_SMALL]  34.28 130.7 180 top
R154  -  [NB_R0402_SMALL]  54.16 129.4 90 bottom
R162  -  [NB_R0402_SMALL]  35.75 120.64 180 top
R163  -  [NB_R0402_SMALL]  34.45 132.2 180 bottom
R166  -  [NB_R0402_SMALL]  34.83 122.44 90 top
R169  -  [VX_R0402_SMALL]  139.38 128.64 0 top
R171  -  [NB_R0402_SMALL]  144.13 136.77 270 top
R172  -  [NB_R0402_SMALL]  143.11 136.77 270 top
R175  -  [VX_R0402_SMALL]  142.81 128.13 180 top
R176  -  [NB_R0402_SMALL]  140.09 123.31 0 top
R178  -  [NB_R0402_SMALL]  141.16 128.64 270 top
R180  -  [VX_R0402_SMALL]  140.27 125.59 0 top
R181  -  [NB_R0603_H24_SMALL]  150.35 128.35 0 bottom
R182  -  [NB_R0402_SMALL]  140.27 126.48 0 top
R183  -  [VX_R0402_SMALL]  144.97 126.73 0 top
R184  -  [NB_R0402_SMALL]  145.81 137.48 180 top
R185  -  [NB_R0402_SMALL]  149.54 128.56 90 top
R195  -  [NB_R0402_SMALL]  176.31 34.97 90 bottom
R196  -  [NB_R0402_SMALL]  169.71 43.02 180 bottom
R208  -  [NB_R0402_SMALL]  34.68 139.28 90 top
R216  -  [NB_R0402_SMALL]  98.87 131.43 270 bottom
R217  -  [NB_R0402_SMALL]  97.98 133.03 90 bottom
R218  -  [NB_R0402_SMALL]  97.98 131.43 90 bottom
R219  -  [NB_R0402_SMALL]  98.84 133.03 270 bottom
R223  -  [NB_R0402_SMALL]  28.88 127.75 180 top
R226  -  [NB_R0402_SMALL]  25.97 128.64 180 top
R227  -  [NB_R0402_SMALL]  29.4 133.72 0 top
R229  -  [NB_R0402_SMALL]  28.88 128.64 180 top
R268  -  [NB_R0402_SMALL]  80.68 125.46 180 top
R272  -  [VX_R0402_SMALL]  155.26 103.87 0 bottom
R282  -  [NB_R0402_SMALL]  269.45 59.83 180 top
R286  -  [NB_R0402_SMALL]  252.51 54.85 0 top
R288  -  [NB_R0402_SMALL]  254.82 61.71 270 top
R292  -  [NB_R0402_SMALL]  252.51 57.39 0 top
R298  -  [NB_R0402_SMALL]  260.28 45.71 90 top
R302  -  [NB_R0402_SMALL]  250.38 54.85 180 top
R309  -  [NB_R0402_SMALL]  262.95 61.96 270 top
R310  -  [NB_R0402_SMALL]  255.71 61.71 270 top
R316  -  [NB_R0402_SHORT_25MIL]  229.42 44.56 90 top
R321  -  [NB_R0402_SMALL]  266.63 45.71 270 top
R322  -  [NB_R0402_SMALL]  250.38 57.14 0 top
R324  -  [NB_R0402_SMALL]  268.29 54.09 180 top
R325  -  [NB_R0402_SMALL]  250.38 58.03 180 top
R327  -  [NB_R0402_SMALL]  222.95 47.61 90 top
R328  -  [NB_R0402_SMALL]  223.96 50 270 top
R329  -  [NB_R0402_SMALL]  226.88 47.49 270 top
R330  -  [NB_R0402_SMALL]  224.85 50 270 top
R332  -  [NB_R0402_SMALL]  222.24 49.95 90 top
R336  -  [NB_R0402_SMALL]  244.41 52.57 180 top
R338  -  [NB_R0402_SMALL]  244.41 51.73 0 top
R339  -  [NB_R0402_SMALL]  225.23 58.6 0 top
R340  -  [NB_R0402_SMALL]  258.94 44.01 0 top
R343  -  [NB_R0402_SMALL]  235.65 67.17 270 top
R344  -  [NB_R0402_SMALL]  244.38 48.93 90 top
R345  -  [NB_R0402_SMALL]  225.23 59.47 0 top
R346  -  [NB_R0402_SMALL]  223.1 49.31 90 top
R347  -  [NB_R0402_SMALL]  223.84 47.61 90 top
R348  -  [NB_R0402_SMALL]  229.04 64.5 270 top
R349  -  [NB_R0402_SMALL]  238.31 64.38 90 top
R350  -  [NB_R0402_SMALL]  228.2 64.5 270 top
R353  -  [NB_R0402_SMALL]  50.05 126.73 0 top
R354  -  [NB_R0402_SMALL]  250.25 52.69 180 top
R355  -  [NB_R0402_SMALL]  237.42 67.17 270 top
R356  -  [NB_R0402_SMALL]  236.54 64.38 270 top
R357  -  [NB_R0402_SMALL]  236.54 67.17 270 top
R359  -  [NB_R0402_SMALL]  228.92 47.11 180 top
R360  -  [NB_R0402_SMALL]  239.2 64.38 90 top
R361  -  [NB_R0402_SMALL]  228.92 46.22 180 top
R362  -  [NB_R0402_SMALL]  245.35 50.89 180 top
R364  -  [NB_R0402_SMALL]  246.19 48.93 270 top
R366  -  [NB_R0402_SMALL]  234 64.38 270 top
R367  -  [NB_R0402_SMALL]  223.71 55.49 180 top
R368  -  [NB_R0402_SMALL]  237.42 64.38 270 top
R370  -  [NB_R0402_SMALL]  225.99 55.49 180 top
R371  -  [NB_R0402_SMALL]  242 56.88 180 top
R372  -  [NB_R0402_SMALL]  245.3 48.93 90 top
R373  -  [NB_R0402_SMALL]  238.31 68.95 270 top
R374  -  [NB_R0402_SMALL]  226.1 64.15 180 top
R375  -  [NB_R0402_SMALL]  227.21 67.43 90 top
R376  -  [NB_R0402_SMALL]  244.41 54.98 180 top
R377  -  [NB_R0402_SMALL]  232.85 68.95 180 top
R378  -  [NB_R0402_SMALL]  227.24 52.58 90 top
R379  -  [NB_R0402_SMALL]  228.53 48.12 180 top
R380  -  [NB_R0402_SMALL]  230.06 67.17 270 top
R381  -  [NB_R0402_SMALL]  224.98 56.5 180 top
R382  -  [NB_R0402_SMALL]  241.95 59.73 180 top
R383  -  [NB_R0402_SMALL]  244.41 58.15 0 top
R384  -  [NB_R0402_SMALL]  230.95 67.17 270 top
R385  -  [NB_R0402_SMALL]  235.52 64.38 270 top
R386  -  [NB_R0402_SMALL]  244.79 37.45 90 top
R388  -  [NB_R0402_SMALL]  147.64 76.32 180 top
R391  -  [NB_R0402_SMALL]  257.49 45.71 90 top
R392  -  [NB_R0402_SMALL]  245.3 36.06 0 top
R393  -  [NB_R0402_SMALL]  222.82 57.47 0 top
R394  -  [NB_R0402_SMALL]  242.61 51.17 180 top
R395  -  [NB_R0402_SMALL]  234.5 67.17 90 top
R396  -  [NB_R0402_SMALL]  232.73 67.17 90 top
R397  -  [NB_R0402_SMALL]  226.25 67.43 90 top
R398  -  [NB_R0402_SMALL]  233.61 67.17 90 top
R399  -  [NB_R0402_SMALL]  222.82 56.58 180 top
R400  -  [NB_R0402_SMALL]  231.84 67.17 270 top
R402  -  [NB_R0402_SMALL]  244.47 64.81 0 top
R403  -  [NB_R0402_SMALL]  247.56 60.39 180 top
R404  -  [NB_R0402_SMALL]  151.7 60.29 180 top
R405  -  [NB_R0402_SMALL]  151.7 64.5 180 top
R406  -  [NB_R0402_SMALL]  225.36 67.17 90 top
R408  -  [NB_R0402_SMALL]  244.41 56.88 180 top
R418  -  [NB_R0402_SMALL]  189.42 91.05 180 top
R419  -  [NB_R0402_SMALL]  262.95 45.71 270 top
R422  -  [NB_R0402_SMALL]  189.42 88.51 180 top
R424  -  [NB_R0402_SMALL]  188.76 95.59 180 top
R427  -  [VX_R0402_SMALL]  258.76 12.18 270 top
R428  -  [NB_R0402_SMALL]  261.17 14.72 180 top
R431  -  [VX_R0402_SMALL]  262.95 11.8 90 top
R432  -  [NB_R0402_SMALL]  261.17 5.2 270 top
R435  -  [NB_R0402_SMALL]  267.9 9.13 180 top
R438  -  [NB_R0402_SMALL]  262.06 5.2 270 top
R441  -  [NB_R0402_SMALL]  151.7 61.11 180 top
R444  -  [NB_R0402_SMALL]  151.7 63.62 180 top
R449  -  [NB_R0402_SMALL]  151.7 62.76 180 top
R450  -  [NB_R0402_SMALL]  151.7 61.94 180 top
R454  -  [NB_R0402_SMALL]  229.17 67.17 90 top
R455  -  [NB_R0402_SMALL]  228.15 67.17 90 top
R460  -  [NB_R0402_SMALL]  16.32 121.15 180 top
R461  -  [NB_R0402_SMALL]  222.44 59.63 0 top
R462  -  [NB_R0402_SMALL]  21.27 117.21 0 bottom
R463  -  [NB_R0402_SMALL]  21.27 118.15 0 bottom
R464  -  [NB_R0402_SMALL]  21.27 114.42 0 bottom
R465  -  [NB_R0402_SMALL]  21.27 109.59 0 bottom
R466  -  [NB_R0402_SMALL]  21.27 115.35 0 bottom
R467  -  [NB_R0402_SMALL]  21.27 112 0 bottom
R468  -  [NB_R0402_SMALL]  21.27 110.48 0 bottom
R469  -  [NB_R0402_SMALL]  21.27 112.89 0 bottom
R470  -  [NB_R0402_SMALL]  20.25 125.21 180 top
R471  -  [NB_R0402_SMALL]  16.32 122.93 180 top
R472  -  [VX_R0402_SMALL]  17.84 125.34 0 top
R473  -  [NB_R0402_SMALL]  17.46 117.84 90 bottom
R474  -  [NB_R0402_SMALL]  16.32 119.37 180 top
R475  -  [NB_R0402_SMALL]  16.32 120.26 180 top
R478  -  [NB_R0402_SMALL]  260.28 5.2 270 top
R479  -  [NB_R0402_SMALL]  126.92 65.39 270 top
R713  -  [NB_R0402_SMALL]  140.09 124.19 180 top
R717  -  [NB_R0402_SMALL]  186.12 50.92 90 bottom
R731  -  [NB_R0402_SMALL]  182.1 56.15 270 top
R732  -  [NB_R0402_SMALL]  182.93 56.15 270 top
R734  -  [NB_R0402_SMALL]  185.23 50.92 90 bottom
R801  -  [NB_R0402_SMALL]  124.17 75.81 270 top
R802  -  [NB_R0402_SMALL]  125.46 75.81 270 top
R803  -  [NB_R0402_SMALL]  127.06 75.93 270 top
R2602  -  [NB_R0402_SHORT]  33.59 108.45 270 top
R2672  -  [NB_R0402_SMALL]  194.68 42.41 270 bottom
R2677  -  [NB_R0402_SMALL]  199.55 45.28 90 bottom
R2704  -  [R0402]  18.29 138.76 180 top
R2720  -  [NB_R0402_H16_SMALL]  182.54 127.01 180 bottom
R2721  -  [NB_R0402_SMALL]  190.31 129.02 90 bottom
R2722  -  [NB_R0402_SMALL]  190.31 126.35 270 bottom
R2723  -  [NB_R0402_SMALL]  191.2 129.02 90 bottom
R2724  -  [NB_R0402_SMALL]  191.2 126.35 270 bottom
R2725  -  [NB_R0402_SMALL]  191.07 135.75 90 bottom
R2726  -  [NB_R0402_SMALL]  190.18 135.75 90 bottom
R2727  -  [NB_R0402_SMALL]  189.29 135.75 90 bottom
R2729  -  [NB_R0402_SMALL]  191.07 133.59 270 bottom
R2730  -  [NB_R0402_SMALL]  190.18 133.59 270 bottom
R2732  -  [NB_R0402_SMALL]  189.29 133.59 270 bottom
R2736  -  [NB_R0402_SMALL]  169.71 42.18 180 bottom
R2739  -  [R1206_H26]  94.6 144.16 270 bottom
R2740  -  [NB_R0402_SMALL]  85.91 144.62 90 bottom
R2741  -  [VX_R0402_SMALL]  81.85 141.09 90 bottom
R2742  -  [NB_R0402_SMALL]  92.16 144.62 90 bottom
R2743  -  [VX_R0402_SMALL]  80.96 141.09 90 bottom
R2744  -  [R0402]  77.98 139.69 180 bottom
R2745  -  [R0402]  72.01 142.66 0 bottom
R2746  -  [R0402]  74.55 140.94 0 bottom
R2747  -  [NB_R0402_H16_SMALL]  85.91 140.7 0 bottom
R2748  -  [NB_R0402_H16_SMALL]  85.91 139.43 0 bottom
R2803  -  [NB_R0402_SMALL]  183.07 139.18 90 top
R2810  -  [NB_R0402_SMALL]  81.35 131.84 180 top
R3603  -  [NB_R0402_SHORT_25MIL]  209.17 142.61 0 bottom
R3701  -  [NB_R0603_H22_SMALL]  260.18 39.33 270 top
R3702  -  [NB_R0402_SMALL]  261.05 26.4 270 top
R3703  -  [NB_R0402_SMALL]  267.12 26.53 270 top
R4104  -  [NB_R0402_SMALL]  55.43 94.98 0 bottom
R7101  -  [NB_R0402_SMALL]  242.3 99.18 270 bottom
R7102  -  [NB_R0402_SMALL]  243.52 98.67 180 bottom
R7103  -  [NB_R0402_SMALL]  243.6 109.94 0 bottom
R7104  -  [NB_R0402_SMALL]  246.57 110.5 270 bottom
R9387  -  [NB_R0402_SMALL]  50.05 125.59 0 top
R9388  -  [VX_R0402_SMALL]  265.87 40.13 0 top
R9394  -  [NB_R0402_SMALL]  270.43 29.45 0 top
R9395  -  [NB_R0402_SMALL]  262.02 26.4 270 top
R9396  -  [NB_R0402_SMALL]  119.16 141.64 180 top
R9398  -  [NB_R0402_SMALL]  261.17 61.96 270 top
R9399  -  [NB_R0402_SMALL]  82.74 38.6 270 top
R9400  -  [NB_R0402_SMALL]  265.75 45.71 270 top
R9401  -  [NB_R0402_SMALL]  160.84 129.27 180 top
R9403  -  [NB_R0402_SMALL]  263.97 45.71 90 top
R9404  -  [NB_R0402_SMALL]  254.57 45.71 90 top
R9405  -  [NB_R0402_SMALL]  252.79 45.71 90 top
R9406  -  [NB_R0402_SMALL]  253.68 45.71 90 top
R9407  -  [NB_R0402_SMALL]  250.38 55.87 180 top
R9408  -  [NB_R0402_SMALL]  256.6 61.71 270 top
R9414  -  [NB_R0402_SMALL]  153.99 126.23 270 bottom
R9415  -  [NB_R0402_SMALL]  252.54 59.81 0 top
R9416  -  [NB_R0402_SMALL]  40.45 99.18 180 bottom
R9417  -  [NB_R0402_SMALL]  252.17 51.68 0 top
R9418  -  [NB_R0402_SMALL]  259.4 45.71 90 top
R9420  -  [NB_R0402_SMALL]  250.38 58.92 180 top
R9421  -  [NB_R0402_SMALL]  250.38 59.81 0 top
R9427  -  [NB_R0402_SMALL]  262.06 23.86 270 top
R9428  -  [NB_R0402_SMALL]  257.49 34.28 180 top
R9429  -  [NB_R0402_SMALL]  257.49 33.39 180 top
R9430  -  [NB_R0402_SMALL]  257.49 32.5 180 top
R9431  -  [NB_R0402_SMALL]  268.03 26.53 270 top
R9435  -  [NB_R0402_SMALL]  131.89 74.82 270 bottom
R9436  -  [NB_R0402_SMALL]  131.04 74.82 270 bottom
R9442  -  [R0402]  18.05 140.91 180 top
R9443  -  [NB_R0402_SMALL]  162.75 136.51 270 top
R9444  -  [NB_R0402_SMALL]  97.93 115.84 180 bottom
R9445  -  [NB_R0402_SMALL]  88.16 109.95 90 bottom
R9446  -  [NB_R0402_SMALL]  89.05 110.2 90 bottom
R9450  -  [VX_R0402_SMALL]  35.85 129.12 0 bottom
R9451  -  [VX_R0402_SMALL]  35.85 129.99 180 bottom
R9452  -  [NB_R0402_SMALL]  35.85 128.23 0 bottom
R9453  -  [NB_R0402_SMALL]  93.58 115.05 0 bottom
R9454  -  [NB_R0402_SMALL]  91.53 110.2 90 bottom
R9458  -  [NB_R0402_SMALL]  189.42 46.11 270 bottom
R9461  -  [NB_R0402_SMALL]  268.29 57.27 0 top
R9462  -  [NB_R0402_SMALL]  27.04 94.73 270 top
R9463  -  [NB_R0402_SMALL]  252.28 50.79 0 top
R9466  -  [NB_R0402_SMALL]  252.28 49.77 0 top
R9483  -  [NB_R0402_SMALL]  28.13 94.73 90 top
R9485  -  [NB_R0402_SMALL]  258.51 45.71 90 top
R9486  -  [NB_R0402_SMALL]  29.02 94.73 90 top
R9488  -  [NB_R0603_H22_SMALL]  50.68 88.33 0 top
R9489  -  [NB_R0402_SMALL]  45.78 90.56 180 top
R9492  -  [NB_R0402_SMALL]  44.26 97.02 270 top
R9493  -  [NB_R0402_SMALL]  44.26 99.3 270 top
R9497  -  [NB_R0402_SMALL]  263.08 5.2 270 top
R9499  -  [VX_R0402_SMALL]  154.24 59.81 270 bottom
R9500  -  [NB_R0402_SMALL]  181.42 84.06 270 top
R9501  -  [NB_R0402_SMALL]  180.48 94.5 270 top
R9502  -  [VX_R0402_SMALL]  154.72 121.73 90 bottom
R9503  -  [VX_R0402_SMALL]  156.75 121.78 90 bottom
R9504  -  [VX_R0402_SMALL]  157.82 121.78 90 bottom
R9505  -  [VX_R0402_SMALL]  158.16 107.96 90 bottom
R9506  -  [VX_R0402_SMALL]  156.64 108.05 90 bottom
R9507  -  [VX_R0402_SMALL]  152.94 110.86 90 bottom
R9508  -  [VX_R0402_SMALL]  144.97 113.32 270 bottom
R9509  -  [VX_R0402_SMALL]  144.97 116.6 270 bottom
R9510  -  [VX_R0402_SMALL]  146.91 120 0 bottom
R9511  -  [VX_R0402_SMALL]  150.51 120 90 bottom
R9512  -  [VX_R0402_SMALL]  159.54 107.96 90 bottom
R9513  -  [VX_R0402_SMALL]  152.09 110.86 90 bottom
R9514  -  [VX_R0402_SMALL]  188.2 139.82 270 bottom
R9520  -  [VX_R0402_SMALL]  186.24 141.17 270 bottom
R9521  -  [VX_R0402_SMALL]  189.49 140.81 270 bottom
R9522  -  [VX_R0402_SMALL]  190.46 139.82 270 bottom
R9523  -  [VX_R0402_SMALL]  195.31 146.85 315 bottom
R9524  -  [VX_R0402_SMALL]  194.04 147.69 270 bottom
R9525  -  [VX_R0402_SMALL]  192.52 140.65 270 bottom
R9526  -  [NB_R0402_SMALL]  191.43 141.26 90 bottom
R9527  -  [NB_R0402_SMALL]  185.74 144.77 0 bottom
R9529  -  [NB_R0402_SMALL]  192.34 146.55 180 top
R9531  -  [NB_R0402_SMALL]  189.04 146.55 0 top
R9532  -  [NB_R0402_SMALL]  190.69 146.55 0 top
R9533  -  [VX_R0402_SMALL]  185.74 145.66 180 bottom
R9534  -  [NB_R0402_SMALL]  185.74 146.55 0 bottom
R9535  -  [NB_R0603_H24_SMALL]  198.18 144.64 90 bottom
R9536  -  [R0402]  134.81 75.17 90 bottom
R9537  -  [NB_R0402_SMALL]  89.39 119.77 270 top
R9538  -  [NB_R0402_SMALL]  90.26 119.77 270 top
R9539  -  [NB_R0402_SMALL]  94.55 135.37 0 top
R9542  -  [NB_R0402_SMALL]  83.88 135.24 0 bottom
R9543  -  [NB_R0402_SMALL]  83.88 134.35 0 bottom
R9544  -  [NB_R0402_SMALL]  93.66 119.27 270 top
R9545  -  [NB_R0402_SMALL]  194.63 145.28 180 bottom
R9546  -  [NB_R0402_SMALL]  96.35 111.98 90 bottom
R9557  -  [NB_R0402_SMALL]  150.93 58.17 270 top
R9560  -  [NB_R0402_SMALL]  157.29 84.95 180 top
R9562  -  [NB_R0402_SMALL]  152.33 86.86 180 top
R9563  -  [NB_R0402_SMALL]  154.62 83.3 180 bottom
R9567  -  [NB_R0402_SMALL]  189.42 86.73 180 top
R9569  -  [NB_R0402_SMALL]  189.42 87.62 180 top
R9570  -  [NB_R0402_SMALL]  94.55 134.48 0 top
R9571  -  [NB_R0402_SMALL]  160.72 121.55 180 bottom
R9572  -  [NB_R0402_SMALL]  261.17 45.71 270 top
R9573  -  [NB_R0402_SMALL]  261.17 44.06 270 top
R9574  -  [NB_R0402_SMALL]  172.71 41.82 180 bottom
R9575  -  [NB_R0402_SMALL]  168.97 35.19 180 bottom
R9576  -  [NB_R0402_SMALL]  164.26 41.87 0 bottom
R9577  -  [NB_R0402_SMALL]  224.47 67.17 90 top
R9578  -  [NB_R0402_SMALL]  178.73 33.97 180 bottom
R9579  -  [NB_R0402_SMALL]  222.79 66.31 0 top
R9580  -  [NB_R0402_SMALL]  190.41 97.63 180 top
R9581  -  [NB_R0402_SMALL]  190.41 96.8 180 top
R9582  -  [NB_R0402_SMALL]  220.99 66.3 180 top
R9583  -  [NB_R0402_SMALL]  241.54 46.14 180 top
R9584  -  [R0402]  225.18 61.76 180 top
R9585  -  [NB_R0402_SMALL]  242.89 46.98 90 top
R9586  -  [NB_R0402_SMALL]  242.5 43.42 0 top
R9587  -  [NB_R0402_SMALL]  243.27 45.71 180 top
R9588  -  [NB_R0402_SMALL]  252.33 46.93 0 top
R9589  -  [NB_R0402_SMALL]  264.86 45.71 90 top
R9591  -  [NB_R0402_SMALL]  267.52 45.71 90 top
R9592  -  [NB_R0402_SMALL]  262.06 61.96 270 top
R9593  -  [NB_R0402_SMALL]  160.34 122.77 270 bottom
R9594  -  [NB_R0402_SMALL]  94.55 130.93 0 top
R9615  -  [NB_R0402_SMALL]  33.18 129.15 180 top
R9616  -  [NB_R0402_SMALL]  36.64 116.19 270 top
R9617  -  [NB_R0402_SMALL]  42 132.17 0 top
R9623  -  [NB_R0402_SMALL]  35.57 125.74 0 bottom
R9624  -  [NB_R0402_SMALL]  35.75 121.76 90 bottom
R9625  -  [VX_R0402_SMALL]  48.83 119.75 0 top
R9626  -  [NB_R0402_SMALL]  44.84 114.9 0 top
R9627  -  [NB_R0402_SMALL]  38.9 128.97 0 top
R9629  -  [R0603_H24]  40.9 116.96 0 bottom
R9631  -  [NB_R0402_SMALL]  46.04 117.5 270 top
R9632  -  [NB_R0402_SMALL]  36.21 133.16 0 top
R9633  -  [NB_R0402_SMALL]  35.57 124.91 180 bottom
R9634  -  [NB_R0402_SMALL]  45.78 127.19 0 bottom
R9635  -  [NB_R0402_SMALL]  38.9 127.95 180 top
R9636  -  [NB_R0402_SMALL]  94.55 133.59 0 top
R9637  -  [NB_R0402_SMALL]  94.55 131.81 0 top
R9638  -  [NB_R0402_SMALL]  185.74 143.75 0 bottom
R9639  -  [NB_R0402_SMALL]  140.27 127.37 0 top
R9640  -  [NB_R0402_SMALL]  154.44 100.06 0 bottom
R9641  -  [VX_R0402_SMALL]  164.31 43.4 180 bottom
R9644  -  [NB_R0402_SMALL]  265.24 7.1 180 top
R9645  -  [NB_R0402_SMALL]  265.24 8.12 180 top
R9646  -  [NB_R0402_SMALL]  266.89 7.1 0 top
R9647  -  [NB_R0402_SMALL]  90.59 113.98 180 top
R9648  -  [NB_R0402_SMALL]  23.56 119.11 270 bottom
R9657  -  [NB_R0402_SMALL]  262.06 45.71 90 top
R9658  -  [NB_R0402_SMALL]  176.49 133.97 270 bottom
R9659  -  [NB_R0402_SMALL]  175.22 133.97 270 bottom
R9660  -  [NB_R0402_SMALL]  168.87 133.97 270 bottom
R9661  -  [NB_R0402_SMALL]  167.6 133.97 270 bottom
R9662  -  [VX_R0402_SMALL]  161.51 43.4 0 bottom
R9668  -  [NB_R0402_SMALL]  47.05 95.49 270 top
R9671  -  [NB_R0402_SMALL]  144.32 62.12 180 top
R9673  -  [NB_R0402_SMALL]  55.41 115.55 270 top
R9674  -  [NB_R0402_SMALL]  240.04 64.38 270 top
R9675  -  [VX_R0402_SMALL]  270.06 37.21 270 top
R9676  -  [VX_R0402_SMALL]  270.95 37.21 270 top
R9677  -  [NB_R0402_SMALL]  88.12 103.95 270 bottom
R9678  -  [NB_R0402_SMALL]  87.29 103.95 270 bottom
R9679  -  [NB_R0402_SMALL]  152.26 96.74 180 bottom
R9680  -  [NB_R0402_SMALL]  152.26 97.63 180 bottom
R9681  -  [VX_R0402_SMALL]  272.48 47.99 180 top
R9682  -  [NB_R0402_SMALL]  97.01 112.79 270 top
R9683  -  [NB_R0402_SMALL]  50.02 87.59 270 bottom
R9684  -  [NB_R0402_SMALL]  253.81 62.12 270 top
R9685  -  [NB_R0402_SMALL]  241.92 44.64 270 top
R9686  -  [NB_R0402_SMALL]  90.74 114.69 180 bottom
R9687  -  [NB_R0402_SMALL]  226.1 64.99 0 top
R9688  -  [NB_R0402_SMALL]  252.28 48.86 0 top
R9689  -  [NB_R0402_SMALL]  248.8 49.49 270 top
R9690  -  [NB_R0402_SMALL]  248.8 51.12 270 top
R9691  -  [NB_R0402_SMALL]  50.05 90.46 270 bottom
R9692  -  [NB_R0402_SMALL]  61.17 120.51 180 top
R9694  -  [NB_R0402_SMALL]  165.29 35.52 90 top
R9695  -  [NB_R0402_SMALL]  165.29 37.17 270 top
R9696  -  [NB_R0402_SMALL]  45.86 111.44 270 bottom
R9697  -  [NB_R0402_SMALL]  44.77 93.71 270 bottom
R9698  -  [NB_R0402_SMALL]  43.5 94.1 180 bottom
RC9  -  [NB_R0402_SMALL]  137.73 65.6 270 top
RC11  -  [NB_R0402_SMALL]  137.93 109.36 90 bottom
RC20  -  [NB_R0402_SMALL]  134.22 109.87 90 top
RC21  -  [NB_R0402_SMALL]  139.38 89.4 0 top
RC23  -  [NB_R0402_SMALL]  136.87 65.6 270 top
RC24  -  [NB_R0402_SMALL]  133.64 66.56 180 top
RC25  -  [NB_R0402_SMALL]  131.99 64.83 270 top
RC26  -  [NB_R0402_SMALL]  131.99 66.54 270 top
RC27  -  [NB_R0402_SMALL]  152.33 81.14 0 bottom
RC28  -  [NB_R0402_SMALL]  143.95 95.03 0 bottom
RC30  -  [NB_R0402_SMALL]  143.95 95.87 0 bottom
RC36  -  [NB_R0402_SMALL]  147.89 93.76 0 bottom
RC37  -  [NB_R0402_SMALL]  147.89 94.96 0 bottom
RC40  -  [NB_R0402_SMALL]  118.5 109.64 180 bottom
RC44  -  [NB_R0402_SMALL]  119.37 108.8 180 bottom
RC45  -  [NB_R0402_SMALL]  135.72 98.67 0 top
RC47  -  [VX_R0402_SMALL]  157.07 82.3 180 top
RC48  -  [NB_R0402_SMALL]  132.73 74.82 90 bottom
RC50  -  [VX_R0402_SMALL]  156.75 79.41 180 top
RC51  -  [VX_R0402_SMALL]  157.08 80.58 180 top
RC52  -  [NB_R0402_SMALL]  110.91 97.83 270 top
RC56  -  [NB_R0402_SMALL]  148.99 58.17 270 top
RC57  -  [NB_R0402_SMALL]  149.92 58.17 270 top
